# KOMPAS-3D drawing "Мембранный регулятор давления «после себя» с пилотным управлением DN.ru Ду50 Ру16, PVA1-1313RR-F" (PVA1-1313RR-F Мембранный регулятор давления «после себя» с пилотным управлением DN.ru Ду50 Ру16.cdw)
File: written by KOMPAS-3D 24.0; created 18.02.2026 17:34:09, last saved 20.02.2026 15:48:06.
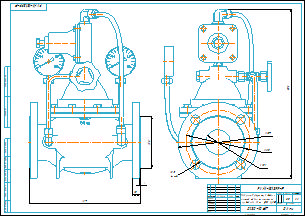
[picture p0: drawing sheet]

Document properties: art: D230-10617; Автор: R2D2; Форматы листов документа: A2; Полное имя файла: PVA1-1313RR-F Мембранный регулятор давления «после себя» с пилотным управлением DN.ru Ду50 Ру16.m3d; Масса: 8.5; Наименование: Мембранный регулятор давления «после себя» с пилотным управлением DN.ru Ду50 Ру16; Количество листов документа: 1; Примечание: D230-10617

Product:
- Part/product: Мембранный регулятор давления «после себя» с пилотным управлением DN.ru Ду50 Ру16  | designation PVA1-1313RR-F
    Масса: 8.5
    Раздел спецификации: Прочие изделия
    Примечание: D230-10617
    additional columns: D230-10617

Referenced files in E:\Работа\Зайцев\Для компаса\: чертеж DN.ru А3.cdt
Referenced files in E:\Работа\Зайцев\PVA1-1313RR-F Мембранный регулятор давления «после себя» с пилотным управлением DN.ru Ду50-200 Ру16\DN50\: PVA1-1313RR-F Мембранный регулятор давления «после себя» с пилотным управлением DN.ru Ду50 Ру16.m3d
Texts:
  чертеж DN.ru А3.cdt
  Мембранный регулятор давления
  «после себя» с пилотным
  управлением DN.ru Ду50 Ру16
  PVA1-1313RR-F
  prop
  Мембранный регулятор давления «после себя» с пилотным управлением DN.ru Ду50 Ру16
  PVA1-1313RR-F Мембранный регулятор давления «после себя» с пилотным управлением DN.ru Ду50 Ру16
Dimensions and other numbers on the sheet: 1:1; 0; 1; 2; 8,5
